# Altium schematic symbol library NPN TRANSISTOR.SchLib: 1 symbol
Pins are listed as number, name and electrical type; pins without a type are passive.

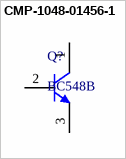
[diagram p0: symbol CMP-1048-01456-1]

## CMP-1048-01456-1
designator Q?, comment BC548B
Amplifier Transistor, NPN Silicon, 3-Pin TO-92, Bulk Box; Manufacturer: On Semiconductor; IC Continuous (A): 0.1; fT Min (MHz): 150
footprint ONSC-TO-92-3-29-11 (TO, 3-Leads, Body Dia 4.7mm, Pitch 1.27mm)
pins: 1 C, 2 B, 3 E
